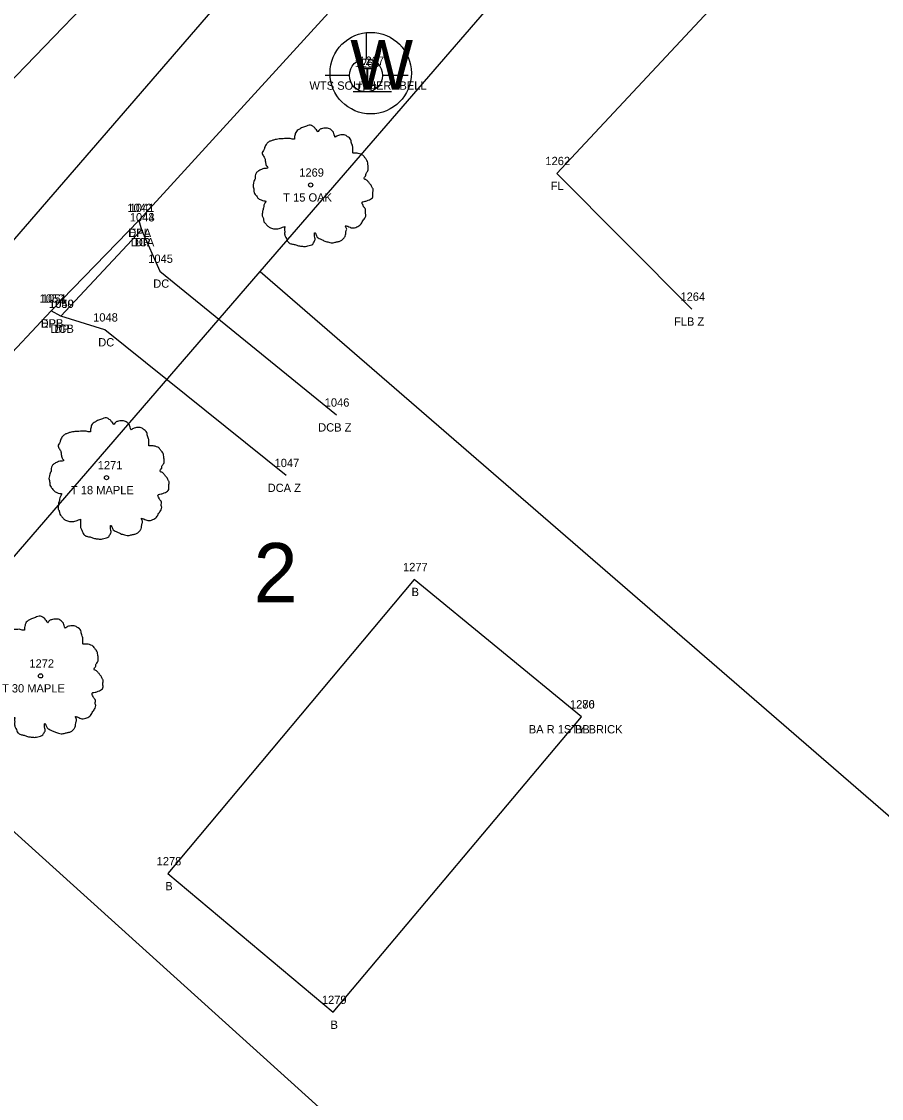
# Model space of a CAD drawing. Extents: x 1812113 to 1819860, y 1177290 to 1181185.
# Drawn here: x 1813885.3 to 1813989, y 1178145.9 to 1178275.6 of the extents above; entities that cross this region are included whole.
import ezdxf

# ---------------------------------------------------------------- set-up
doc = ezdxf.new("R2010")
doc.units = 0
for name, color, linetype in [('RD_EX_Bldg', 7, 'Continuous'), ('RD_EX_Bldg_txCode', 7, 'Continuous'), ('RD_EX_Conc', 7, 'Continuous'), ('RD_EX_Conc_txCode', 7, 'Continuous'), ('RD_EX_Driveway', 7, 'Continuous'), ('RD_EX_Driveway_txCode', 7, 'Continuous'), ('RD_EX_DV_Prop', 7, 'Continuous'), ('RD_EX_DV_TX_Prop', 7, 'Continuous'), ('RD_EX_Fence_Other', 7, 'Continuous'), ('RD_EX_Fence_Other_txCode', 7, 'Continuous'), ('RD_EX_Road', 7, 'Continuous'), ('RD_EX_Road_txCode', 7, 'Continuous'), ('RD_EX_UT', 7, 'Continuous'), ('RD_EX_UT_txCode', 7, 'Continuous'), ('RD_EX_VEG', 7, 'Continuous'), ('RD_EX_VEG_txCode', 7, 'Continuous'), ('RD_HC_CL', 7, 'Continuous'), ('RD_SMD_Locator', 7, 'Continuous')]:
    doc.layers.add(name, color=color, linetype=linetype)

msp = doc.modelspace()

# ---------------------------------------------------------------- linework, layer by layer
at = {"layer": 'RD_EX_Bldg'}
msp.add_lwpolyline([(1813952.83, 1178191.89), (1813932.67, 1178208.43), (1813902.97, 1178173), (1813922.9, 1178156.3), (1813952.83, 1178191.89)], dxfattribs=at)
at = {"layer": 'RD_EX_Conc'}
for points in [[(1813899.79, 1178250.56), (1813902, 1178245.57), (1813923.3, 1178228.25)], [(1813917.24, 1178220.97), (1813895.37, 1178238.5), (1813890.08, 1178240.14)]]:
    msp.add_lwpolyline(points, dxfattribs=at)
at = {"layer": 'RD_EX_Driveway'}
msp.add_lwpolyline([(1813899.48, 1178251.69), (1813899.79, 1178250.56), (1813890.08, 1178240.14), (1813888.9, 1178240.78)], dxfattribs=at)
at = {"layer": 'RD_EX_DV_Prop'}
for p, q in [((1813914.12, 1178245.52), (1814044.97, 1178396.77)), ((1813868.31, 1178192.56), (1813914.12, 1178245.52)), ((1813914.12, 1178245.52), (1814088.82, 1178094.39)), ((1813868.31, 1178192.56), (1814033.95, 1178043.26))]:
    msp.add_line(p, q, dxfattribs=at)
at = {"layer": 'RD_EX_Fence_Other'}
msp.add_lwpolyline([(1814039.17, 1178321.6), (1814032.91, 1178334.96), (1814018.04, 1178330.3), (1813949.86, 1178257.34), (1813966.14, 1178241)], dxfattribs=at)
at = {"layer": 'RD_EX_Road'}
for p, q in [((1813874.69, 1178258.74), (1813910.02, 1178295.38)), ((1813927.09, 1178281.88), (1813899.48, 1178251.69)), ((1813899.48, 1178251.69), (1813888.9, 1178240.78)), ((1813888.9, 1178240.78), (1813846.63, 1178195.79))]:
    msp.add_line(p, q, dxfattribs=at)
at = {"layer": 'RD_EX_UT'}
for p, q in [((1813926.87, 1178274.22), (1813926.87, 1178271.15)), ((1813921.94, 1178269.17), (1813924.87, 1178269.17)), ((1813928.87, 1178269.17), (1813931.94, 1178269.17)), ((1813925.31, 1178267.21), (1813929.94, 1178267.21))]:
    msp.add_line(p, q, dxfattribs=at)
for centre, radius in [((1813927.44, 1178269.42), 4.91), ((1813926.87, 1178269.15), 2)]:
    msp.add_circle(centre, radius, dxfattribs=at)
at = {"layer": 'RD_EX_VEG'}
for centre, radius in [((1813920.19, 1178255.95), 0.25), ((1813920.17, 1178255.94), 0.0001), ((1813895.59, 1178220.7), 0.25), ((1813895.58, 1178220.69), 0.0001), ((1813887.64, 1178196.82), 0.25), ((1813887.63, 1178196.81), 0.0001)]:
    msp.add_circle(centre, radius, dxfattribs=at)
for points in [[(1813920.32, 1178263.12), (1813920.02, 1178263.15), (1813919.69, 1178263.05), (1813919.44, 1178262.95), (1813919.22, 1178262.87), (1813918.99, 1178262.77), (1813918.69, 1178262.6), (1813918.47, 1178262.4), (1813918.34, 1178262.15), (1813918.29, 1178261.92), (1813918.24, 1178261.65), (1813918.24, 1178261.47), (1813918.12, 1178261.45), (1813917.97, 1178261.47), (1813917.72, 1178261.55), (1813917.47, 1178261.55), (1813917.22, 1178261.55), (1813916.87, 1178261.52), (1813916.52, 1178261.52), (1813916.25, 1178261.47), (1813915.92, 1178261.42), (1813915.55, 1178261.3), (1813915.2, 1178261.17), (1813914.9, 1178260.92), (1813914.65, 1178260.45), (1813914.52, 1178260.1), (1813914.37, 1178259.85), (1813914.52, 1178259.4), (1813914.7, 1178259.05), (1813914.72, 1178258.85), (1813914.8, 1178258.42), (1813914.9, 1178258.2), (1813915.02, 1178258), (1813914.95, 1178257.97), (1813914.57, 1178257.92), (1813914.27, 1178257.82), (1813913.85, 1178257.6), (1813913.62, 1178257.37), (1813913.52, 1178257.05), (1813913.5, 1178256.7), (1813913.4, 1178256.5), (1813913.32, 1178256.22), (1813913.3, 1178256.15), (1813913.25, 1178255.82), (1813913.35, 1178255.37), (1813913.37, 1178255.02), (1813913.5, 1178254.8), (1813913.65, 1178254.63), (1813913.82, 1178254.38), (1813914.22, 1178254.15), (1813914.55, 1178254.05), (1813914.75, 1178254.03), (1813914.57, 1178253.53), (1813914.52, 1178253.18), (1813914.4, 1178252.78), (1813914.4, 1178252.7), (1813914.35, 1178252.23), (1813914.5, 1178251.9), (1813914.57, 1178251.53), (1813914.75, 1178251.3), (1813915.02, 1178251), (1813915.35, 1178250.78), (1813915.85, 1178250.65), (1813916.25, 1178250.68), (1813916.82, 1178250.85), (1813917.07, 1178250.93), (1813917.04, 1178250.75), (1813917.07, 1178250.38), (1813917.07, 1178249.95), (1813917.22, 1178249.63), (1813917.32, 1178249.35), (1813917.47, 1178249.1), (1813917.79, 1178248.88), (1813918.19, 1178248.8), (1813918.62, 1178248.65), (1813919.07, 1178248.58), (1813919.57, 1178248.55), (1813920.17, 1178248.7), (1813920.44, 1178248.83), (1813920.54, 1178249), (1813920.74, 1178249.38), (1813920.69, 1178249.6), (1813920.72, 1178250.2), (1813920.82, 1178250.03), (1813920.99, 1178249.68), (1813921.49, 1178249.38), (1813921.89, 1178249.2), (1813922.37, 1178249.05), (1813922.67, 1178248.98), (1813923.14, 1178249.05), (1813923.52, 1178249.13), (1813923.89, 1178249.25), (1813924.19, 1178249.53), (1813924.37, 1178249.8), (1813924.42, 1178250.08), (1813924.49, 1178250.45), (1813924.54, 1178250.63)], [(1813924.54, 1178250.63), (1813924.47, 1178250.8), (1813924.42, 1178251.05), (1813924.49, 1178251.03), (1813924.67, 1178250.98), (1813924.94, 1178250.85), (1813925.17, 1178250.78), (1813925.49, 1178250.8), (1813925.77, 1178250.9), (1813926.22, 1178251.18), (1813926.49, 1178251.65), (1813926.77, 1178252.05), (1813926.84, 1178252.38), (1813926.79, 1178252.6), (1813926.77, 1178253.1), (1813926.57, 1178253.35), (1813926.52, 1178253.48), (1813926.42, 1178253.88), (1813926.49, 1178253.93), (1813926.77, 1178253.98), (1813927.14, 1178254.1), (1813927.42, 1178254.23), (1813927.64, 1178254.4), (1813927.71, 1178254.63), (1813927.69, 1178255.02), (1813927.74, 1178255.42), (1813927.67, 1178255.57), (1813927.57, 1178255.72), (1813927.49, 1178255.92), (1813927.34, 1178256.07), (1813927.24, 1178256.22), (1813927.14, 1178256.32), (1813927.02, 1178256.47), (1813926.84, 1178256.6), (1813926.69, 1178256.65), (1813926.64, 1178256.8), (1813926.79, 1178257), (1813926.84, 1178257.1), (1813926.87, 1178257.32), (1813927.09, 1178257.67), (1813927.14, 1178258.07), (1813927.09, 1178258.5), (1813927.04, 1178258.77), (1813926.89, 1178259.05), (1813926.69, 1178259.3), (1813926.57, 1178259.47), (1813926.39, 1178259.6), (1813926.07, 1178259.72), (1813925.82, 1178259.77), (1813925.47, 1178259.77), (1813925.27, 1178259.82), (1813925.29, 1178259.87), (1813925.29, 1178260.02), (1813925.29, 1178260.3), (1813925.22, 1178260.75), (1813925.07, 1178261.25), (1813925.07, 1178261.27), (1813924.97, 1178261.52), (1813924.74, 1178261.72), (1813924.57, 1178261.82), (1813924.37, 1178261.95), (1813924.12, 1178261.97), (1813923.82, 1178261.97), (1813923.54, 1178261.92), (1813923.34, 1178261.82), (1813923.17, 1178261.7), (1813923.09, 1178261.85), (1813922.99, 1178262.15), (1813922.94, 1178262.3), (1813922.79, 1178262.47), (1813922.57, 1178262.67), (1813922.12, 1178262.8), (1813921.49, 1178262.72), (1813921.19, 1178262.52), (1813921.04, 1178262.35), (1813920.99, 1178262.47), (1813920.79, 1178262.67), (1813920.69, 1178262.85), (1813920.52, 1178262.97), (1813920.37, 1178263.07), (1813920.27, 1178263.12)], [(1813895.72, 1178227.87), (1813895.42, 1178227.9), (1813895.1, 1178227.8), (1813894.85, 1178227.7), (1813894.62, 1178227.62), (1813894.4, 1178227.52), (1813894.1, 1178227.35), (1813893.87, 1178227.15), (1813893.75, 1178226.9), (1813893.7, 1178226.67), (1813893.65, 1178226.4), (1813893.65, 1178226.22), (1813893.52, 1178226.2), (1813893.37, 1178226.22), (1813893.12, 1178226.3), (1813892.87, 1178226.3), (1813892.62, 1178226.3), (1813892.27, 1178226.27), (1813891.92, 1178226.27), (1813891.65, 1178226.22), (1813891.32, 1178226.17), (1813890.95, 1178226.05), (1813890.6, 1178225.92), (1813890.3, 1178225.67), (1813890.05, 1178225.2), (1813889.92, 1178224.85), (1813889.77, 1178224.6), (1813889.92, 1178224.15), (1813890.1, 1178223.8), (1813890.12, 1178223.6), (1813890.2, 1178223.17), (1813890.3, 1178222.95), (1813890.42, 1178222.75), (1813890.35, 1178222.72), (1813889.97, 1178222.67), (1813889.67, 1178222.57), (1813889.25, 1178222.35), (1813889.02, 1178222.12), (1813888.92, 1178221.8), (1813888.9, 1178221.45), (1813888.8, 1178221.25), (1813888.72, 1178220.97), (1813888.7, 1178220.9), (1813888.65, 1178220.58), (1813888.75, 1178220.13), (1813888.77, 1178219.78), (1813888.9, 1178219.55), (1813889.05, 1178219.38), (1813889.22, 1178219.13), (1813889.62, 1178218.9), (1813889.95, 1178218.8), (1813890.15, 1178218.78), (1813889.97, 1178218.28), (1813889.92, 1178217.93), (1813889.8, 1178217.53), (1813889.8, 1178217.45), (1813889.75, 1178216.98), (1813889.9, 1178216.65), (1813889.97, 1178216.28), (1813890.15, 1178216.05), (1813890.42, 1178215.75), (1813890.75, 1178215.53), (1813891.25, 1178215.4), (1813891.65, 1178215.43), (1813892.22, 1178215.6), (1813892.47, 1178215.68), (1813892.45, 1178215.5), (1813892.47, 1178215.13), (1813892.47, 1178214.7), (1813892.62, 1178214.38), (1813892.72, 1178214.1), (1813892.87, 1178213.85), (1813893.2, 1178213.63), (1813893.6, 1178213.55), (1813894.02, 1178213.4), (1813894.47, 1178213.33), (1813894.97, 1178213.3), (1813895.57, 1178213.45), (1813895.85, 1178213.58), (1813895.95, 1178213.75), (1813896.15, 1178214.13), (1813896.1, 1178214.35), (1813896.12, 1178214.95), (1813896.22, 1178214.78), (1813896.4, 1178214.43), (1813896.9, 1178214.13), (1813897.29, 1178213.95), (1813897.77, 1178213.8), (1813898.07, 1178213.73), (1813898.54, 1178213.8), (1813898.92, 1178213.88), (1813899.29, 1178214), (1813899.59, 1178214.28), (1813899.77, 1178214.55), (1813899.82, 1178214.83), (1813899.89, 1178215.2), (1813899.94, 1178215.38)], [(1813899.94, 1178215.38), (1813899.87, 1178215.55), (1813899.82, 1178215.8), (1813899.89, 1178215.78), (1813900.07, 1178215.73), (1813900.34, 1178215.6), (1813900.57, 1178215.53), (1813900.89, 1178215.55), (1813901.17, 1178215.65), (1813901.62, 1178215.93), (1813901.89, 1178216.4), (1813902.17, 1178216.8), (1813902.24, 1178217.13), (1813902.19, 1178217.35), (1813902.17, 1178217.85), (1813901.97, 1178218.1), (1813901.92, 1178218.23), (1813901.82, 1178218.63), (1813901.89, 1178218.68), (1813902.17, 1178218.73), (1813902.54, 1178218.85), (1813902.82, 1178218.98), (1813903.04, 1178219.15), (1813903.12, 1178219.38), (1813903.09, 1178219.78), (1813903.14, 1178220.18), (1813903.07, 1178220.33), (1813902.97, 1178220.48), (1813902.89, 1178220.68), (1813902.74, 1178220.82), (1813902.64, 1178220.97), (1813902.54, 1178221.07), (1813902.42, 1178221.22), (1813902.24, 1178221.35), (1813902.09, 1178221.4), (1813902.04, 1178221.55), (1813902.19, 1178221.75), (1813902.24, 1178221.85), (1813902.27, 1178222.07), (1813902.49, 1178222.42), (1813902.54, 1178222.82), (1813902.49, 1178223.25), (1813902.44, 1178223.52), (1813902.29, 1178223.8), (1813902.09, 1178224.05), (1813901.97, 1178224.22), (1813901.79, 1178224.35), (1813901.47, 1178224.47), (1813901.22, 1178224.52), (1813900.87, 1178224.52), (1813900.67, 1178224.57), (1813900.69, 1178224.62), (1813900.69, 1178224.77), (1813900.69, 1178225.05), (1813900.62, 1178225.5), (1813900.47, 1178226), (1813900.47, 1178226.02), (1813900.37, 1178226.27), (1813900.14, 1178226.47), (1813899.97, 1178226.57), (1813899.77, 1178226.7), (1813899.52, 1178226.72), (1813899.22, 1178226.72), (1813898.94, 1178226.67), (1813898.74, 1178226.57), (1813898.57, 1178226.45), (1813898.49, 1178226.6), (1813898.39, 1178226.9), (1813898.34, 1178227.05), (1813898.19, 1178227.22), (1813897.97, 1178227.42), (1813897.52, 1178227.55), (1813896.9, 1178227.47), (1813896.6, 1178227.27), (1813896.45, 1178227.1), (1813896.4, 1178227.22), (1813896.2, 1178227.42), (1813896.1, 1178227.6), (1813895.92, 1178227.72), (1813895.77, 1178227.82), (1813895.67, 1178227.87)], [(1813887.77, 1178203.99), (1813887.47, 1178204.02), (1813887.15, 1178203.92), (1813886.9, 1178203.82), (1813886.67, 1178203.74), (1813886.45, 1178203.64), (1813886.15, 1178203.47), (1813885.92, 1178203.27), (1813885.8, 1178203.02), (1813885.75, 1178202.79), (1813885.7, 1178202.52), (1813885.7, 1178202.34), (1813885.57, 1178202.32), (1813885.42, 1178202.34), (1813885.17, 1178202.42), (1813884.92, 1178202.42), (1813884.67, 1178202.42), (1813884.32, 1178202.39), (1813883.97, 1178202.39), (1813883.7, 1178202.34), (1813883.37, 1178202.29), (1813883, 1178202.17), (1813882.65, 1178202.04), (1813882.35, 1178201.79), (1813882.1, 1178201.32), (1813881.97, 1178200.97), (1813881.82, 1178200.72), (1813881.97, 1178200.27), (1813882.15, 1178199.92), (1813882.17, 1178199.72), (1813882.25, 1178199.29), (1813882.35, 1178199.07), (1813882.47, 1178198.87), (1813882.4, 1178198.84), (1813882.02, 1178198.79), (1813881.72, 1178198.69), (1813881.3, 1178198.47), (1813881.07, 1178198.24), (1813880.97, 1178197.92), (1813880.95, 1178197.57), (1813880.85, 1178197.37), (1813880.77, 1178197.09), (1813880.75, 1178197.02), (1813880.7, 1178196.69), (1813880.8, 1178196.24), (1813880.82, 1178195.89), (1813880.95, 1178195.67), (1813881.1, 1178195.5), (1813881.27, 1178195.25), (1813881.67, 1178195.02), (1813882, 1178194.92), (1813882.2, 1178194.9), (1813882.02, 1178194.4), (1813881.97, 1178194.05), (1813881.85, 1178193.65), (1813881.85, 1178193.57), (1813881.8, 1178193.1), (1813881.95, 1178192.77), (1813882.02, 1178192.4), (1813882.2, 1178192.17), (1813882.47, 1178191.87), (1813882.8, 1178191.65), (1813883.3, 1178191.52), (1813883.7, 1178191.55), (1813884.27, 1178191.72), (1813884.52, 1178191.8), (1813884.5, 1178191.62), (1813884.52, 1178191.25), (1813884.52, 1178190.82), (1813884.67, 1178190.5), (1813884.77, 1178190.22), (1813884.92, 1178189.97), (1813885.25, 1178189.75), (1813885.65, 1178189.67), (1813886.07, 1178189.52), (1813886.52, 1178189.45), (1813887.02, 1178189.42), (1813887.62, 1178189.57), (1813887.9, 1178189.7), (1813888, 1178189.87), (1813888.2, 1178190.25), (1813888.15, 1178190.47), (1813888.17, 1178191.07), (1813888.27, 1178190.9), (1813888.45, 1178190.55), (1813888.95, 1178190.25), (1813889.34, 1178190.07), (1813889.82, 1178189.92), (1813890.12, 1178189.85), (1813890.59, 1178189.92), (1813890.97, 1178190), (1813891.34, 1178190.12), (1813891.64, 1178190.4), (1813891.82, 1178190.67), (1813891.87, 1178190.95), (1813891.94, 1178191.32), (1813891.99, 1178191.5)], [(1813891.99, 1178191.5), (1813891.92, 1178191.67), (1813891.87, 1178191.92), (1813891.94, 1178191.9), (1813892.12, 1178191.85), (1813892.39, 1178191.72), (1813892.62, 1178191.65), (1813892.94, 1178191.67), (1813893.22, 1178191.77), (1813893.67, 1178192.05), (1813893.94, 1178192.52), (1813894.22, 1178192.92), (1813894.29, 1178193.25), (1813894.24, 1178193.47), (1813894.22, 1178193.97), (1813894.02, 1178194.22), (1813893.97, 1178194.35), (1813893.87, 1178194.75), (1813893.94, 1178194.8), (1813894.22, 1178194.85), (1813894.59, 1178194.97), (1813894.87, 1178195.1), (1813895.09, 1178195.27), (1813895.17, 1178195.5), (1813895.14, 1178195.89), (1813895.19, 1178196.29), (1813895.12, 1178196.44), (1813895.02, 1178196.59), (1813894.94, 1178196.79), (1813894.79, 1178196.94), (1813894.69, 1178197.09), (1813894.59, 1178197.19), (1813894.47, 1178197.34), (1813894.29, 1178197.47), (1813894.14, 1178197.52), (1813894.09, 1178197.67), (1813894.24, 1178197.87), (1813894.29, 1178197.97), (1813894.32, 1178198.19), (1813894.54, 1178198.54), (1813894.59, 1178198.94), (1813894.54, 1178199.37), (1813894.49, 1178199.64), (1813894.34, 1178199.92), (1813894.14, 1178200.17), (1813894.02, 1178200.34), (1813893.84, 1178200.47), (1813893.52, 1178200.59), (1813893.27, 1178200.64), (1813892.92, 1178200.64), (1813892.72, 1178200.69), (1813892.74, 1178200.74), (1813892.74, 1178200.89), (1813892.74, 1178201.17), (1813892.67, 1178201.62), (1813892.52, 1178202.12), (1813892.52, 1178202.14), (1813892.42, 1178202.39), (1813892.19, 1178202.59), (1813892.02, 1178202.69), (1813891.82, 1178202.82), (1813891.57, 1178202.84), (1813891.27, 1178202.84), (1813890.99, 1178202.79), (1813890.79, 1178202.69), (1813890.62, 1178202.57), (1813890.54, 1178202.72), (1813890.44, 1178203.02), (1813890.39, 1178203.17), (1813890.24, 1178203.34), (1813890.02, 1178203.54), (1813889.57, 1178203.67), (1813888.95, 1178203.59), (1813888.65, 1178203.39), (1813888.5, 1178203.22), (1813888.45, 1178203.34), (1813888.25, 1178203.54), (1813888.15, 1178203.72), (1813887.97, 1178203.84), (1813887.82, 1178203.94), (1813887.72, 1178203.99)]]:
    msp.add_spline(points, degree=3, dxfattribs=at)
at = {"layer": 'RD_HC_CL'}
msp.add_line((1814048.02, 1178438.51), (1813851.74, 1178211.63), dxfattribs=at)
at = {"layer": 'RD_SMD_Locator'}
for centre in [(1813949.86, 1178257.34), (1813899.48, 1178251.69), (1813899.48, 1178251.69), (1813899.79, 1178250.56), (1813899.79, 1178250.56), (1813902, 1178245.57), (1813966.14, 1178241), (1813888.9, 1178240.78), (1813888.9, 1178240.78), (1813890.08, 1178240.14), (1813890.08, 1178240.14), (1813895.37, 1178238.5), (1813923.3, 1178228.25), (1813917.24, 1178220.97), (1813932.67, 1178208.43), (1813952.83, 1178191.89), (1813952.83, 1178191.89), (1813902.97, 1178173), (1813922.9, 1178156.3)]:
    msp.add_circle(centre, 0.001, dxfattribs=at)

# ---------------------------------------------------------------- texts
at = {"layer": 'RD_EX_Bldg_txCode'}
for s, p in [('1277', (1813931.33, 1178209.43)), ('B', (1813932.36, 1178206.43)), ('1280', (1813951.45, 1178192.89)), ('1276', (1813951.46, 1178192.89)), ('BA R 1STY BRICK', (1813946.49, 1178189.89)), ('BB', (1813952.05, 1178189.89)), ('1278', (1813901.63, 1178174)), ('B', (1813902.67, 1178171)), ('1279', (1813921.55, 1178157.3)), ('B', (1813922.59, 1178154.3))]:
    msp.add_text(s, height=1, dxfattribs=at).set_placement(p)
at = {"layer": 'RD_EX_Conc_txCode'}
for s, p in [('1044', (1813898.4, 1178251.56)), ('DCA', (1813898.52, 1178248.56)), ('1045', (1813900.62, 1178246.57)), ('DC', (1813901.22, 1178243.57)), ('1049', (1813888.69, 1178241.14)), ('1048', (1813893.98, 1178239.5)), ('DCB', (1813888.83, 1178238.14)), ('DC', (1813894.59, 1178236.5)), ('1046', (1813921.89, 1178229.25)), ('DCB Z', (1813921.1, 1178226.25)), ('1047', (1813915.85, 1178221.97)), ('DCA Z', (1813915.01, 1178218.97))]:
    msp.add_text(s, height=1, dxfattribs=at).set_placement(p)
at = {"layer": 'RD_EX_Driveway_txCode'}
for s, p in [('1042', (1813898.1, 1178252.69)), ('1043', (1813898.4, 1178251.56)), ('DPA', (1813898.21, 1178249.69)), ('DP', (1813899.01, 1178248.56)), ('1051', (1813887.8, 1178241.78)), ('1050', (1813888.65, 1178241.14)), ('DPB', (1813887.65, 1178238.78)), ('DP', (1813889.3, 1178238.14))]:
    msp.add_text(s, height=1, dxfattribs=at).set_placement(p)
at = {"layer": 'RD_EX_DV_TX_Prop'}
msp.add_text('2', height=7.14, dxfattribs=at).set_placement((1813913.32, 1178205.68))
at = {"layer": 'RD_EX_Fence_Other_txCode'}
for s, p in [('1262', (1813948.49, 1178258.34)), ('FL', (1813949.13, 1178255.34)), ('1264', (1813964.77, 1178242)), ('FLB Z', (1813963.99, 1178239))]:
    msp.add_text(s, height=1, dxfattribs=at).set_placement(p)
at = {"layer": 'RD_EX_Road_txCode'}
for s, p in [('1041', (1813898.38, 1178252.69)), ('EPL', (1813898.28, 1178249.69)), ('1052', (1813887.52, 1178241.78)), ('EPL', (1813887.7, 1178238.78))]:
    msp.add_text(s, height=1, dxfattribs=at).set_placement(p)
at = {"layer": 'RD_EX_UT'}
for s, height, p in [('W', 6, (1813924.97, 1178267.42)), ('T', 2, (1813926.2, 1178268.11))]:
    msp.add_text(s, height=height, dxfattribs=at).set_placement(p)
at = {"layer": 'RD_EX_UT_txCode'}
for s, p in [('1268', (1813925.5, 1178270.15)), ('1267', (1813926.07, 1178270.42)), ('WTS SOUTHERNBELL', (1813920.05, 1178267.42)), ('TPP', (1813925.6, 1178267.15))]:
    msp.add_text(s, height=1, dxfattribs=at).set_placement(p)
at = {"layer": 'RD_EX_VEG_txCode'}
for s, p in [('1269', (1813918.82, 1178256.95)), ('T 15 OAK', (1813916.89, 1178253.95)), ('1271', (1813894.53, 1178221.7)), ('T 18 MAPLE', (1813891.3, 1178218.7)), ('1272', (1813886.29, 1178197.82)), ('T 30 MAPLE', (1813882.99, 1178194.82))]:
    msp.add_text(s, height=1, dxfattribs=at).set_placement(p)

doc.saveas('drawing.dxf')
